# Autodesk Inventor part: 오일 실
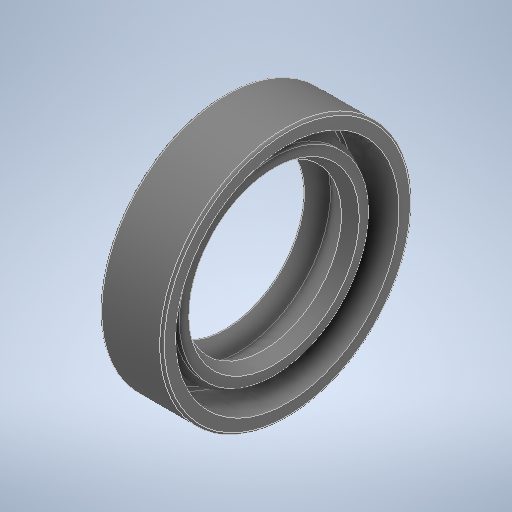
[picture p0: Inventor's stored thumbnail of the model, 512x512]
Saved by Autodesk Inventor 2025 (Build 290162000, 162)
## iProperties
Created: 2024-08
Part Number: 오일 실
Material: 고무
Description: 오일-실
Document SubType Name: Modeling
Designer: 학생
Density: 0.93 g/cm^3
Appearance: 기본값
Author: jhkim
Sending System: Autodesk Inventor 2025
Preprocessor: ST-DEVELOPER v20
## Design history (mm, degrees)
feature "Solid1"
node "솔리드1"
